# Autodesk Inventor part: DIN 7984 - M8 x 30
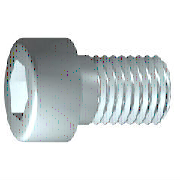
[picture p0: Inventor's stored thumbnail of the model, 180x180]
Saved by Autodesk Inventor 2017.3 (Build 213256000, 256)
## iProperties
Created: 2016-02
Part Number: DIN 7984 - M8 x 30
Material: Acier, doux
Description: Vis à tête cylindrique
Document SubType Name: Modeling
Standard: DIN 7984
Designer: TJ
Standard Revision: 2009-06
Standards Organization: DIN
Language: fr-FR
Size Designation: M8 x 30
Categories: <MemberInstance><Categories><Category DisplayName="Visserie" InternalName="e4da775c-781d-43d5-af7c-5136215cf5a6" Mnemonic="FSTN"><Category DisplayName="Vis" Int
Density: 7.85 g/cm^3
Appearance: Semi-poli
IsCustomPart: 0
Author: TJ
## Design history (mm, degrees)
sketch "Esquisse1"
  geometry: L1 (0.467, 0)-(30, 0); L2 (30, 0)-(30, 4); L3 (30, 4)-(3.75, 4); L4 (3.75, 4)-(2.983, 4); L5 (2.983, 4)-(0, 4); L6 (0, 4)-(0, 6.5); L7 (0, 6.5)-(-5, 6.5); L8 (-5, 6.5)-(-5, 2.887); L9 (-5, 2.887)-(-1.2, 2.887); L10 (-1.2, 2.887)-(0.467, 0); L11 (-12, 0)-(37, 0) reference; L12 (0, -1.3)-(0, 7.8) reference; L13 (3.75, 4)-(0, 4)
  constraints: 22 end point, 6 parallel, 2 collinear, 2 perpendicular, 1 horizontal, 1 point on line
  dimensions: "d1" = 26.25 distance from line of L3.end L2 (= GEL); "d2" = 0.76691 distance of L4.end L3.end (computed from GAL); "d3" = 5 distance between parallel lines of L8 L6 (= KOH); "d4" = 3.8 distance of L8.end L9.end (= INTI); "d5" = 60 deg angle of L10 L1; "d6" = 8 diameter of L3 L1 (= GD); "d7" = 8 diameter of L5 L1 (= BDM); "d8" = 5.7735 diameter of L9 L1 (= 1.1547 x SW); "d9" = 13 diameter of L7 L1 (= KOD); "d26" = 30 distance between parallel lines of L12 L2 (= NLG)
revolve "Corps" sketch "Esquisse1" stored, may be unused: angle "d10" = 90 deg
sketch "Esquisse2"
  geometry: L1 (0, -9.1)-(0, 9.1) reference; L2 (-9.1, 0)-(9.1, 0) reference; L3 (2.887, 0)-(1.443, -2.5); L4 (1.443, -2.5)-(-1.443, -2.5); L5 (-1.443, -2.5)-(-2.887, 0); L6 (-2.887, 0)-(-1.443, 2.5); L7 (-1.443, 2.5)-(1.443, 2.5); L8 (1.443, 2.5)-(2.887, 0); 2 further points
  constraints: 12 end point, 1 coincident, 1 horizontal alignment, 1 point on line, 12 other
extrude "Rainure" join sketch "Esquisse2" stored distance "d11" = 10; taper "d12" = 0 deg
workplane "Work Plane1"
fillet "Fillet2" dims "d30" = 0.1 (= R)
body "Solid1"
fillet "Congé1" dims "d17" = 0.8 (= RR)
feature "Filetage" dims "d13" = 26.25 (= GEL), "d14" = 0
chamfer "Chanfrein1" distance "d15" = 0.76681 (= -0.5 x SPD + 0.5 x GD); stored, may be unused: second distance "d16" = 0.76681 (= GUL), angle "d27" = 45 deg
other parameters: "GD" = 8 (= NND) [user parameter; used in 2 equation terms], "NLG" = 30 [user parameter; used in 1 equation term], "GEL" = 26.25 [user parameter; used in 2 equation terms], "KOD" = 13 [user parameter; used in 1 equation term], "KOH" = 5 [user parameter; used in 1 equation term], "INTI" = 3.8 [user parameter; used in 1 equation term], "GAL" = 0.76681 (= 0.61345 x PTC) [user parameter; used in 1 equation term], "GUL" = 0.76681 (= 0.61345 x PTC) [user parameter; used in 1 equation term], "BDM" = 8 (= NND) [user parameter; used in 1 equation term], "SW" = 5 [user parameter; used in 2 equation terms], "RR" = 0.8 [user parameter; used in 1 equation term], "SPD" = 6.46637 (= NND - 1.2269 x PTC) [user parameter; used in 1 equation term], "d19" = 0, "d28" = 0, "d29" = 0, "R" = 0.1 [user parameter; used in 1 equation term], "TOA" = 30 deg [user parameter], "GD1" = 6.46637 (= THREADDIA - 1.2269 x PTC) [user parameter], "THREADDIA" = 8 [user parameter; used in 1 equation term], "FAWI" = 45 deg [user parameter], "ANG" = 120 deg [user parameter], "TPU" = 8 (computed from PTC) [user parameter], "PTC" = 1.25 [user parameter; used in 5 equation terms], "NND" = 8 [user parameter; used in 3 equation terms], "E0" = 5.775 (= 1.155 x SW) [user parameter]
